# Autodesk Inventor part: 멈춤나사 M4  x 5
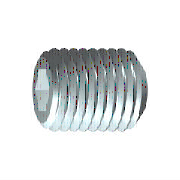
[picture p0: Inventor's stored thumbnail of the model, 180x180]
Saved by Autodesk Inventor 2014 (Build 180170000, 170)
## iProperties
IsCustomPart: 1
Created: 2012-02
Part Number: 멈춤나사 M4  x 5
Material: 강철, 연강
Description: 6각 소켓 머리 없는 멈춤 나사
Document SubType Name: Modeling
Standard: KS B 1028
Designer: mduedu
Standards Organization: KS
Language: ko-KR
Size Designation: 납작점M4x5
Categories: <MemberInstance><Categories><Category DisplayName="조임쇠" InternalName="e4da775c-781d-43d5-af7c-5136215cf5a6" Mnemonic="FSTN"><Category DisplayName="볼트" InternalN
Density: 7.86 g/cm^3
Appearance: 노란색
Mass: 0.401763 g
Surface Area: 0.994256 cm^2
Volume: 0.0511149 cm^3
Author: mduedu
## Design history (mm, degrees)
sketch "스케치1"
  geometry: L1 (0, 0)-(1.833, 0); L2 (5, 1.155)-(5, 2); L3 (5, 2)-(0, 2); L4 (5, 1.155)-(2.5, 1.155); L5 (2.5, 1.155)-(1.833, 0); L6 (0, -0.4)-(0, 2.4) reference; L7 (0, 2)-(0, 0)
  constraints: 13 end point, 3 parallel, 1 collinear, 1 perpendicular, 1 point on line
  dimensions: "d0" = 2.5 distance of L2.start L4.end (= INTI); "d1" = 60 deg angle of L5 L1; "d2" = 4 diameter of L3 L1 (= NND); "d3" = 2.3094 diameter of L4 L1 (= 1.1547 x SW); "d5" = 5 distance from line of L2 L3.end (= NLG)
revolve "본체" sketch "스케치1" stored, may be unused: angle "d6" = 90 deg
sketch "스케치2"
  geometry: L1 (-0.577, 1)-(0.577, 1); L2 (0.577, 1)-(1.155, 0); L3 (1.155, 0)-(0.577, -1); L4 (0.577, -1)-(-0.577, -1); L5 (-0.577, -1)-(-1.155, 0); L6 (-1.155, 0)-(-0.577, 1); A1 r 1.155 centre (0, 0) between (-0.577, 1) and (0.577, 1) reference; 2 further points
  constraints: 12 end point, 2 point on circle, 1 coincident, 1 horizontal, 11 other
extrude "슬롯" join sketch "스케치2" taper "d9" = 0 deg; stored distance "d21" = 10
workaxis "Work Axis1"
workplane "Work Plane1"
body "Solid1"
chamfer "모따기1" distance "d7" = 0.42941 (= -0.5 x GD1 + 0.5 x NND); stored, may be unused: angle "d8" = 45 deg (= FAWI), second distance "d29" = 0.42941 (= -0.5 x GD1 + 0.5 x NND)
feature "스레드" dims "d11" = 5 (= NLG), "d12" = 0
chamfer "모따기2" distance "d13" = 0.42941 (= -0.5 x GD1 + 0.5 x NND); stored, may be unused: angle "d14" = 45 deg (= FAWI), second distance "d30" = 0.42941 (= -0.5 x GD1 + 0.5 x NND)
other parameters: "NND" = 4 [user parameter; used in 5 equation terms], "NLG" = 5 [user parameter; used in 2 equation terms], "INTI" = 2.5 [user parameter; used in 1 equation term], "FAWI" = 45 deg [user parameter; used in 2 equation terms], "SW" = 2 [user parameter; used in 2 equation terms], "GD1" = 3.14117 (= THREADDIA - 1.2269 x PTC) [user parameter; used in 4 equation terms], "d4" = 0, "FAWI1" = 45 deg [user parameter], "d15" = 0, "d31" = 0, "GUL" = 0.42941 (= 0.61345 x PTC) [user parameter], "SPD" = 2.5 [user parameter], "TPU" = 14.28571 (computed from PTC) [user parameter], "TOA" = 30 deg [user parameter], "THREADDIA" = 4 [user parameter; used in 1 equation term], "PTC" = 0.7 [user parameter; used in 4 equation terms], "GAL" = 0.42941 (= 0.61345 x PTC) [user parameter], "E0" = 2.31 (= 1.155 x SW) [user parameter]
